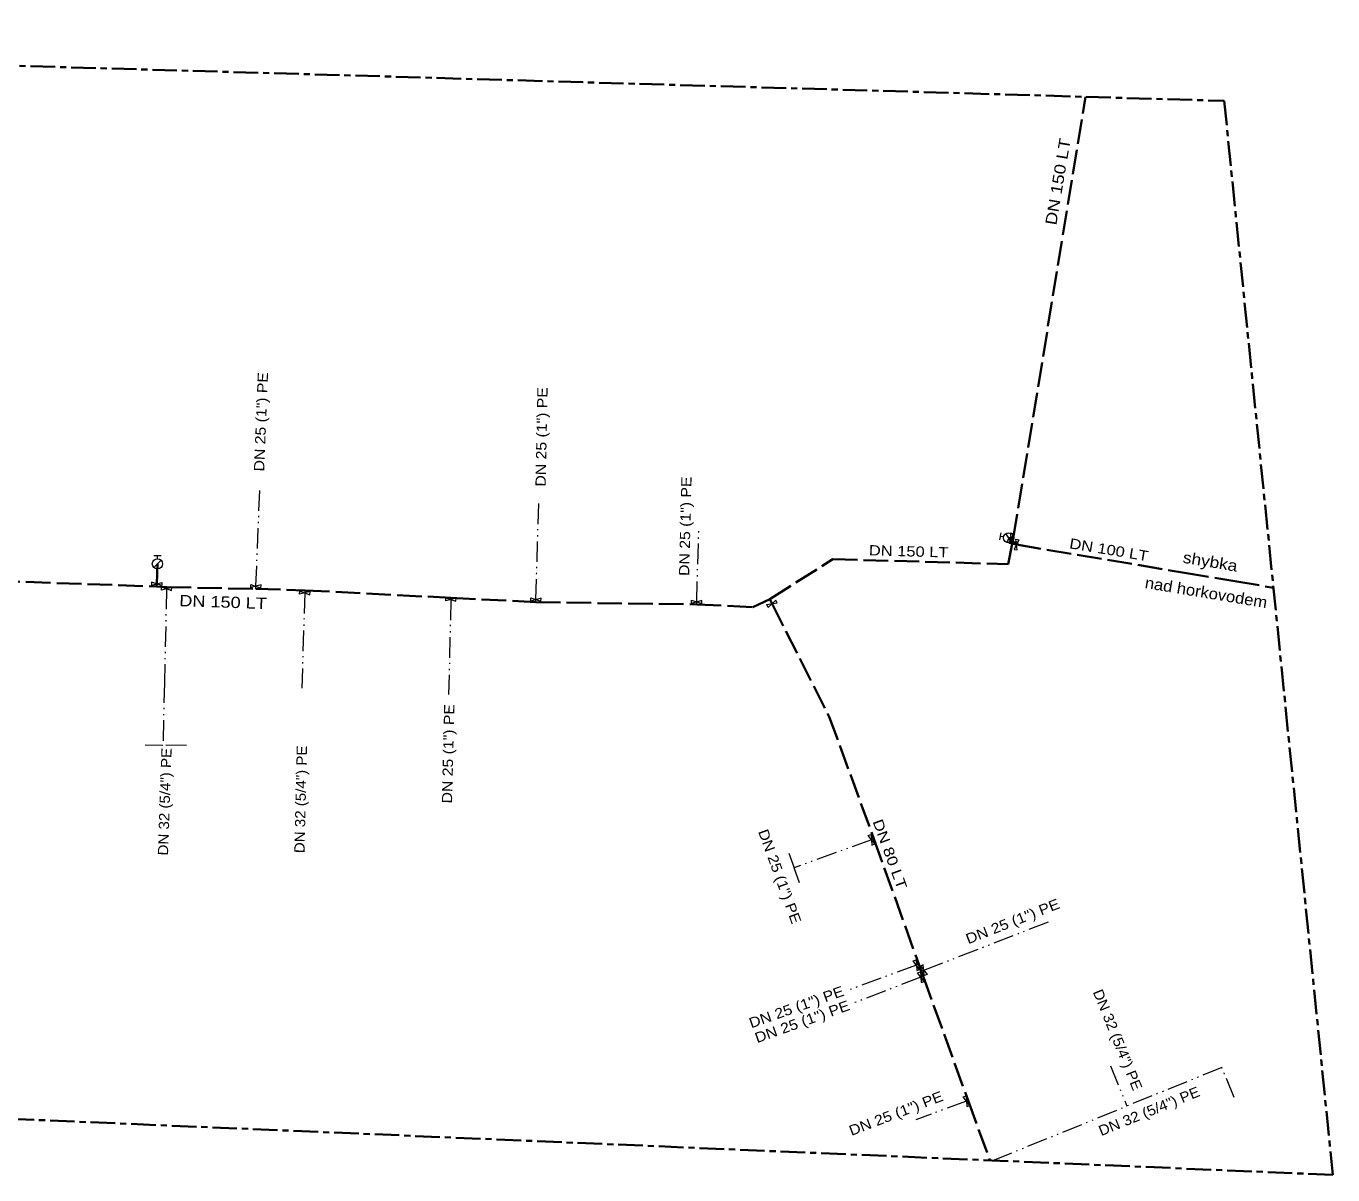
# Model space of a CAD drawing. Extents: x -640241 to -639979, y -1041483 to -1041371.
# Drawn here: x -640106.8 to -639979.5, y -1041482.8 to -1041370.7 of the extents above; entities that cross this region are included whole.
import ezdxf
from ezdxf.enums import TextEntityAlignment as Align

# ---------------------------------------------------------------- set-up
doc = ezdxf.new("R2010")
doc.units = 0
doc.header["$LTSCALE"] = 0.4
for name, pattern in [('DASH_DOUBLE_DOT', [9.2, 5, -1.2, 0.3, -1.2, 0.3, -1.2]), ('LONG_DASH_SHORT_DASH', [9.9, 6, -1.2, 1.5, -1.2]), ('LONG_DASHED', [7.5, 6, -1.5])]:
    doc.linetypes.add(name, pattern=pattern)
for name, color, linetype, lineweight in [('1', 7, 'LONG_DASH_SHORT_DASH', 35), ('10', 7, 'Continuous', 13), ('21', 7, 'LONG_DASHED', 35), ('22', 7, 'DASH_DOUBLE_DOT', 35), ('32', 7, 'DASH_DOUBLE_DOT', 13)]:
    doc.layers.add(name, color=color, linetype=linetype, lineweight=lineweight)
doc.layers.add('29', color=7, linetype='Continuous')
doc.layers.add('39', color=7, linetype='Continuous')

msp = doc.modelspace()

# ---------------------------------------------------------------- linework, layer by layer
at = {"layer": '1'}
msp.add_lwpolyline([(-639990.066, -1041378.027), (-639979.473, -1041482.75), (-640226.879, -1041472.267), (-640241.004, -1041370.744)], close=True, dxfattribs=at)
at = {"layer": '10'}
for p, q in [((-640011.921, -1041420.841), (-640011.795, -1041420.152)), ((-640010.785, -1041421.051), (-640011.355, -1041420.229)), ((-640011.563, -1041420.55), (-640011.858, -1041420.496)), ((-640094.404, -1041423.527), (-640093.697, -1041422.82)), ((-640094.4, -1041422.373), (-640093.7, -1041422.373)), ((-640094.05, -1041422.673), (-640094.05, -1041422.373))]:
    msp.add_line(p, q, dxfattribs=at)
for points in [[(-640010.775, -1041421.196), (-640010.907, -1041420.16), (-640010.611, -1041420.21), (-640011.071, -1041421.147)], [(-640011.212, -1041421.055), (-640010.169, -1041421.006), (-640010.241, -1041421.296), (-640011.139, -1041420.765)], [(-640010.25, -1041421.818), (-640010.389, -1041420.783), (-640010.093, -1041420.83), (-640010.547, -1041421.771)], [(-640094.625, -1041425.262), (-640093.615, -1041424.998), (-640093.626, -1041425.298), (-640094.614, -1041424.962)], [(-640083.946, -1041425.234), (-640084.957, -1041425.494), (-640084.945, -1041425.194), (-640083.958, -1041425.534)], [(-640092.655, -1041425.47), (-640093.666, -1041425.73), (-640093.654, -1041425.43), (-640092.667, -1041425.769)], [(-640079.175, -1041425.88), (-640080.186, -1041426.139), (-640080.174, -1041425.84), (-640079.187, -1041426.18)], [(-640064.939, -1041426.523), (-640065.951, -1041426.782), (-640065.939, -1041426.482), (-640064.952, -1041426.823)], [(-640056.657, -1041426.52), (-640057.663, -1041426.801), (-640057.657, -1041426.501), (-640056.663, -1041426.82)], [(-640033.761, -1041426.701), (-640034.519, -1041427.419), (-640034.654, -1041427.151), (-640033.626, -1041426.969)], [(-640040.979, -1041426.734), (-640041.982, -1041427.025), (-640041.979, -1041426.725), (-640040.982, -1041427.034)], [(-640024.125, -1041450.486), (-640024.756, -1041449.654), (-640024.475, -1041449.549), (-640024.406, -1041450.591)], [(-640019.755, -1041462.716), (-640020.386, -1041461.884), (-640020.105, -1041461.779), (-640020.036, -1041462.821)], [(-640019.679, -1041462.395), (-640019.033, -1041463.215), (-640019.312, -1041463.325), (-640019.4, -1041462.284)], [(-640019.327, -1041463.888), (-640019.958, -1041463.056), (-640019.677, -1041462.951), (-640019.608, -1041463.993)], [(-640014.872, -1041475.981), (-640015.503, -1041475.149), (-640015.222, -1041475.044), (-640015.153, -1041476.086)]]:
    msp.add_lwpolyline(points, close=True, dxfattribs=at)
for centre in [(-640011.0706, -1041420.6394), (-640094.0498, -1041423.1727)]:
    msp.add_circle(centre, 0.5, dxfattribs=at)
at = {"layer": '21'}
for p, q in [((-640010.638, -1041420.712), (-640003.576, -1041377.635)), ((-640010.724, -1041421.232), (-640010.32, -1041421.3)), ((-640010.69, -1041421.03), (-640010.638, -1041420.712)), ((-640010.32, -1041421.3), (-639993.948, -1041424.045)), ((-640115.856, -1041424.63), (-640094.129, -1041425.38)), ((-640094.129, -1041425.38), (-640093.156, -1041425.45)), ((-640079.672, -1041425.76), (-640065.441, -1041426.487)), ((-640065.441, -1041426.487), (-640057.165, -1041426.91)), ((-640034.34, -1041426.609), (-640034.14, -1041427.06)), ((-640057.165, -1041426.91), (-640041.485, -1041427.13)), ((-640024.205, -1041449.984), (-640019.835, -1041462.213)), ((-640019.835, -1041462.213), (-640019.588, -1041462.896)), ((-640019.588, -1041462.896), (-640019.41, -1041463.387)), ((-640019.41, -1041463.387), (-640015.023, -1041475.499)), ((-640015.023, -1041475.499), (-640012.909, -1041481.333))]:
    msp.add_line(p, q, dxfattribs=at)
for points in [[(-640034.34, -1041426.609), (-640028.941, -1041423.176), (-640028.211, -1041422.715), (-640011.113, -1041423.201), (-640010.724, -1041421.232)], [(-640011.07, -1041420.64), (-640010.841, -1041420.678), (-640010.638, -1041420.712)], [(-640010.724, -1041421.232), (-640010.69, -1041421.03), (-640010.69, -1041421.03)], [(-639993.948, -1041424.045), (-639989.017, -1041424.871), (-639985.264, -1041425.5)], [(-640093.156, -1041425.45), (-640084.46, -1041425.614), (-640079.672, -1041425.76)], [(-640041.485, -1041427.13), (-640036.001, -1041427.387), (-640034.34, -1041426.609)], [(-640034.14, -1041427.06), (-640028.566, -1041438.074), (-640024.205, -1041449.984)]]:
    msp.add_lwpolyline(points, dxfattribs=at)
at = {"layer": '22'}
msp.add_lwpolyline([(-640094.129, -1041425.38), (-640094.12, -1041425.13), (-640094.12, -1041425.13), (-640094.05, -1041423.173)], dxfattribs=at)
at = {"layer": '32'}
for p, q in [((-640084.452, -1041425.364), (-640084.065, -1041415.697)), ((-640084.46, -1041425.614), (-640084.452, -1041425.364)), ((-640093.156, -1041425.45), (-640093.16, -1041425.6)), ((-640079.68, -1041426.01), (-640079.985, -1041435.3)), ((-640079.672, -1041425.76), (-640079.68, -1041426.01)), ((-640065.445, -1041426.652), (-640065.666, -1041435.906)), ((-640065.441, -1041426.487), (-640065.445, -1041426.652)), ((-640093.371, -1041434.736), (-640093.512, -1041440.846)), ((-640095.245, -1041440.806), (-640093.512, -1041440.846)), ((-640091.231, -1041440.899), (-640093.512, -1041440.846)), ((-640024.44, -1041450.07), (-640031.988, -1041452.819)), ((-640024.205, -1041449.984), (-640024.44, -1041450.07)), ((-640032.506, -1041451.396), (-640031.988, -1041452.819)), ((-640031.452, -1041454.291), (-640031.988, -1041452.819)), ((-640019.356, -1041462.805), (-640006.758, -1041457.898)), ((-640020.07, -1041462.3), (-640026.571, -1041464.693)), ((-640019.835, -1041462.213), (-640020.07, -1041462.3)), ((-640019.642, -1041463.472), (-640026.071, -1041465.96)), ((-640019.41, -1041463.387), (-640019.642, -1041463.472)), ((-640019.588, -1041462.896), (-640019.356, -1041462.805)), ((-640001.147, -1041472.122), (-639999.554, -1041476.046)), ((-640012.61, -1041481.346), (-639999.554, -1041476.046))]:
    msp.add_line(p, q, dxfattribs=at)
for points in [[(-640057.165, -1041426.91), (-640057.16, -1041426.66), (-640056.881, -1041417.28)], [(-640041.485, -1041427.13), (-640041.48, -1041426.88), (-640041.285, -1041419.885)], [(-640093.16, -1041425.6), (-640093.37, -1041434.701), (-640093.371, -1041434.736)], [(-639989.098, -1041475.216), (-639990.288, -1041472.285), (-639999.554, -1041476.046)], [(-640015.023, -1041475.499), (-640015.187, -1041475.565), (-640020.134, -1041477.383)]]:
    msp.add_lwpolyline(points, dxfattribs=at)

# ---------------------------------------------------------------- texts
at = {"layer": '29'}
for s, height, rotation, width, p in [('DN 150 LT', 1.1, 80.47, 1.2, (-640005.7297, -1041385.9941)), ('DN 150 LT', 1, 358.372, 1.2, (-640020.8342, -1041422.4485)), ('DN 100 LT', 1, 350.557, 1.2, (-640001.382, -1041422.2873)), ('shybka', 1.1, 350.484, 1.15, (-639991.5109, -1041423.4977)), ('nad horkovodem', 1.1, 350.587, 1.1, (-639991.911, -1041426.509)), ('DN 150 LT', 1.1, 358.023, 1.2, (-640087.668, -1041427.439)), ('DN 80 LT', 1, 290.111, 1.25, (-640023.1195, -1041451.6511))]:
    msp.add_text(s, height=height, rotation=rotation, dxfattribs=dict(at, width=width)).set_placement(p, align=Align.CENTER)
at = {"layer": '39'}
for s, rotation, width, p in [('DN 25 (1") PE', 87.707, 1.15, (-640083.457, -1041409.34)), ('DN 25 (1") PE', 88.848, 1.15, (-640056.111, -1041410.8031)), ('DN 25 (1") PE', 88.57, 1.15, (-640042.0992, -1041419.5165)), ('DN 25 (1") PE', 88.632, 1.15, (-640065.2157, -1041441.7009)), ('DN 32 (5/4") PE', 88.032, 1.1, (-640092.8374, -1041446.3802)), ('DN 32 (5/4") PE', 88.679, 1.1, (-640079.5907, -1041446.1465)), ('DN 25 (1") PE', 290.008, 1.15, (-640033.8533, -1041453.8239)), ('DN 25 (1") PE', 21.522, 1.15, (-640010.5054, -1041458.4915)), ('DN 25 (1") PE', 19.388, 1.15, (-640031.598, -1041466.8539)), ('DN 32 (5/4") PE', 292.095, 1.1, (-640000.91, -1041469.7719)), ('DN 25 (1") PE', 19.718, 1.15, (-640031.0367, -1041468.2766)), ('DN 25 (1") PE', 21.017, 1.15, (-640021.8793, -1041477.2189)), ('DN 32 (5/4") PE', 22.094, 1.1, (-639997.1961, -1041477.0002))]:
    msp.add_text(s, height=1, rotation=rotation, dxfattribs=dict(at, width=width)).set_placement(p, align=Align.CENTER)

doc.saveas('drawing.dxf')
